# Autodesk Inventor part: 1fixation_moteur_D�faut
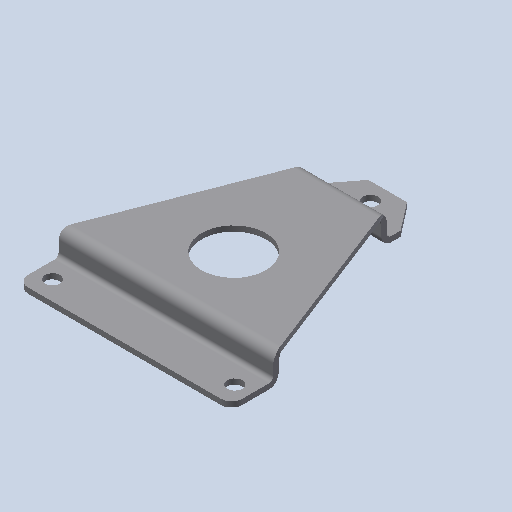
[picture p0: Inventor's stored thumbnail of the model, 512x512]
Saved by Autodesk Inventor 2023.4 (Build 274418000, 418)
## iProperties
Created: 2011-01
Part Number: 1fixation_moteur_D�faut
Document SubType Name: Modeling
Designer: eric
Density: 1 g/cm^3
Mass: 21.7424 g
Surface Area: 188.248 cm^2
Volume: 21.7424 cm^3
Material: Générique
Appearance: Par défaut
Author: eric
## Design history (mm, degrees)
feature "Base1"
node "Corps solides"
node "Corps surfaciques"
node "Solide1"
